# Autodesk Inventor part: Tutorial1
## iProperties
Shininess: 64.0
Length Units: 11269
Angle Units: 11279
Time Units: 11290
Mass Units: 11283
Length Display Precision: 3
Angle Display Precision: 2
Compacted: True
Part Number: Tutorial1
Document SubType Name: Modeling
Created: 2002-12
Designer: deepak
Density: 1 g/cm^3
Density: 0.0
Volumn: 0.0
Area: 0.0
PropertySet Name: Model Information
Control State: 0
Master: False
Checked Out: False
Author: deepak
